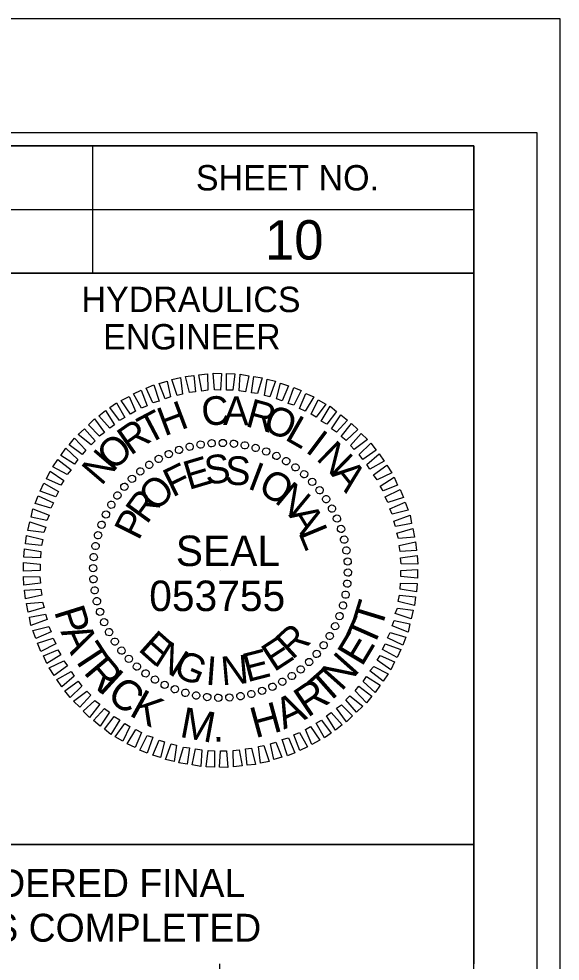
# Model space of a CAD drawing. Extents: x 1629737 to 1631945, y 1172886 to 1173986.
# Drawn here: x 1631314.8 to 1631421.3, y 1173800.4 to 1173985.9 of the extents above; entities that cross this region are included whole.
import ezdxf

# ---------------------------------------------------------------- set-up
doc = ezdxf.new("R2010")
doc.units = 0
for name, color, linetype in [('Sheet Data Field CELL', 7, 'Continuous'), ('Sheet PE Seal Cell', 7, 'Continuous'), ('Sheet Plot Border Inside CELL', 7, 'Continuous'), ('Sheet Plot Border Outside CELL', 7, 'Continuous'), ('Sheet Profile CELL', 7, 'Continuous'), ('Sheet Profile Grid Major CELL', 7, 'Continuous'), ('Sheet Sticker Exception Certification CELL', 7, 'Continuous')]:
    doc.layers.add(name, color=color, linetype=linetype)

msp = doc.modelspace()

# ---------------------------------------------------------------- linework, layer by layer
at = {"layer": 'Sheet PE Seal Cell'}
for p, q in [((1631350.58, 1173902.1), (1631350.58, 1173902.1)), ((1631352.73, 1173902.4), (1631352.73, 1173902.4)), ((1631354.93, 1173902.45), (1631354.93, 1173902.45)), ((1631357.13, 1173902.3), (1631357.13, 1173902.3)), ((1631344.28, 1173900.3), (1631344.28, 1173900.3)), ((1631346.28, 1173901.1), (1631346.28, 1173901.1)), ((1631348.38, 1173901.7), (1631348.38, 1173901.7)), ((1631359.28, 1173901.95), (1631359.28, 1173901.95)), ((1631361.38, 1173901.5), (1631361.38, 1173901.5)), ((1631363.48, 1173900.8), (1631363.48, 1173900.8)), ((1631342.33, 1173899.3), (1631342.33, 1173899.3)), ((1631365.48, 1173899.9), (1631365.48, 1173899.9)), ((1631367.43, 1173898.9), (1631367.43, 1173898.9)), ((1631338.68, 1173896.9), (1631338.68, 1173896.9)), ((1631340.43, 1173898.15), (1631340.43, 1173898.15)), ((1631369.23, 1173897.65), (1631369.23, 1173897.65)), ((1631337.03, 1173895.4), (1631337.03, 1173895.4)), ((1631370.98, 1173896.3), (1631370.98, 1173896.3)), ((1631372.53, 1173894.8), (1631372.53, 1173894.8)), ((1631335.53, 1173893.85), (1631335.53, 1173893.85)), ((1631374.03, 1173893.15), (1631374.03, 1173893.15)), ((1631334.18, 1173892.1), (1631334.18, 1173892.1)), ((1631375.28, 1173891.4), (1631375.28, 1173891.4)), ((1631332.93, 1173890.3), (1631332.93, 1173890.3)), ((1631376.43, 1173889.5), (1631376.43, 1173889.5)), ((1631331.93, 1173888.35), (1631331.93, 1173888.35)), ((1631377.43, 1173887.55), (1631377.43, 1173887.55)), ((1631331.03, 1173886.35), (1631331.03, 1173886.35)), ((1631378.23, 1173885.55), (1631378.23, 1173885.55)), ((1631330.33, 1173884.25), (1631330.33, 1173884.25)), ((1631329.88, 1173882.15), (1631329.88, 1173882.15)), ((1631378.83, 1173883.45), (1631378.83, 1173883.45)), ((1631329.53, 1173880), (1631329.53, 1173880)), ((1631379.23, 1173881.25), (1631379.23, 1173881.25)), ((1631379.53, 1173879.1), (1631379.53, 1173879.1)), ((1631329.38, 1173877.8), (1631329.38, 1173877.8)), ((1631354.48, 1173877.35), (1631354.48, 1173877.35)), ((1631379.58, 1173876.9), (1631379.58, 1173876.9)), ((1631329.43, 1173875.6), (1631329.43, 1173875.6)), ((1631379.43, 1173874.7), (1631379.43, 1173874.7)), ((1631329.73, 1173873.45), (1631329.73, 1173873.45)), ((1631379.08, 1173872.55), (1631379.08, 1173872.55)), ((1631330.13, 1173871.25), (1631330.13, 1173871.25)), ((1631330.73, 1173869.15), (1631330.73, 1173869.15)), ((1631378.63, 1173870.45), (1631378.63, 1173870.45)), ((1631331.53, 1173867.15), (1631331.53, 1173867.15)), ((1631377.93, 1173868.35), (1631377.93, 1173868.35)), ((1631332.53, 1173865.2), (1631332.53, 1173865.2)), ((1631377.03, 1173866.35), (1631377.03, 1173866.35)), ((1631333.68, 1173863.3), (1631333.68, 1173863.3)), ((1631376.03, 1173864.4), (1631376.03, 1173864.4)), ((1631334.93, 1173861.55), (1631334.93, 1173861.55)), ((1631374.78, 1173862.6), (1631374.78, 1173862.6)), ((1631336.43, 1173859.9), (1631336.43, 1173859.9)), ((1631373.43, 1173860.85), (1631373.43, 1173860.85)), ((1631337.98, 1173858.4), (1631337.98, 1173858.4)), ((1631370.28, 1173857.8), (1631370.28, 1173857.8)), ((1631371.93, 1173859.3), (1631371.93, 1173859.3)), ((1631339.73, 1173857.05), (1631339.73, 1173857.05)), ((1631341.53, 1173855.8), (1631341.53, 1173855.8)), ((1631368.53, 1173856.55), (1631368.53, 1173856.55)), ((1631343.48, 1173854.8), (1631343.48, 1173854.8)), ((1631345.48, 1173853.9), (1631345.48, 1173853.9)), ((1631364.68, 1173854.4), (1631364.68, 1173854.4)), ((1631366.63, 1173855.4), (1631366.63, 1173855.4)), ((1631347.58, 1173853.2), (1631347.58, 1173853.2)), ((1631349.68, 1173852.75), (1631349.68, 1173852.75)), ((1631351.83, 1173852.4), (1631351.83, 1173852.4)), ((1631354.03, 1173852.25), (1631354.03, 1173852.25)), ((1631356.23, 1173852.3), (1631356.23, 1173852.3)), ((1631358.38, 1173852.6), (1631358.38, 1173852.6)), ((1631360.58, 1173853), (1631360.58, 1173853)), ((1631362.68, 1173853.6), (1631362.68, 1173853.6))]:
    msp.add_line(p, q, dxfattribs=at)
for points in [[(1631345.98, 1173911.8), (1631344.93, 1173914.95), (1631346.63, 1173915.3), (1631347.03, 1173912.05)], [(1631348.38, 1173912.35), (1631347.58, 1173915.55), (1631349.23, 1173915.7), (1631349.58, 1173912.5)], [(1631350.78, 1173912.65), (1631350.23, 1173915.85), (1631351.93, 1173916.05), (1631351.98, 1173912.8)], [(1631353.28, 1173912.9), (1631353.03, 1173916.15), (1631354.68, 1173916.1), (1631354.48, 1173912.85)], [(1631355.68, 1173912.85), (1631355.68, 1173916.1), (1631357.33, 1173916.05), (1631356.88, 1173912.8)], [(1631358.18, 1173912.7), (1631358.38, 1173915.95), (1631360.03, 1173915.65), (1631359.38, 1173912.5)], [(1631360.58, 1173912.3), (1631361.03, 1173915.5), (1631362.68, 1173915.25), (1631361.78, 1173912.15)], [(1631341.13, 1173910.35), (1631339.83, 1173913.25), (1631341.33, 1173913.85), (1631342.38, 1173910.65)], [(1631343.58, 1173911.15), (1631342.43, 1173914.15), (1631343.98, 1173914.6), (1631344.63, 1173911.5)], [(1631363.13, 1173911.75), (1631363.63, 1173915), (1631365.33, 1173914.6), (1631364.18, 1173911.5)], [(1631365.53, 1173911.1), (1631366.28, 1173914.2), (1631367.83, 1173913.7), (1631366.58, 1173910.75)], [(1631367.78, 1173910.2), (1631368.93, 1173913.35), (1631370.33, 1173912.75), (1631368.93, 1173909.85)], [(1631336.78, 1173908.1), (1631334.93, 1173910.8), (1631336.48, 1173911.6), (1631337.73, 1173908.7)], [(1631338.93, 1173909.3), (1631337.33, 1173912.1), (1631338.88, 1173912.8), (1631340.03, 1173909.75)], [(1631370.03, 1173909.25), (1631371.28, 1173912.2), (1631372.83, 1173911.5), (1631371.13, 1173908.7)], [(1631334.58, 1173906.85), (1631332.73, 1173909.4), (1631334.03, 1173910.35), (1631335.68, 1173907.45)], [(1631372.33, 1173908.1), (1631373.68, 1173910.95), (1631375.18, 1173910.1), (1631373.28, 1173907.5)], [(1631374.28, 1173906.75), (1631376.03, 1173909.65), (1631377.33, 1173908.6), (1631375.38, 1173906.15)], [(1631332.68, 1173905.35), (1631330.53, 1173907.75), (1631331.88, 1173908.8), (1631333.63, 1173906)], [(1631376.33, 1173905.25), (1631378.18, 1173908), (1631379.48, 1173906.9), (1631377.28, 1173904.55)], [(1631330.68, 1173903.8), (1631328.48, 1173906), (1631329.68, 1173907.2), (1631331.63, 1173904.5)], [(1631378.23, 1173903.7), (1631380.28, 1173906.3), (1631381.48, 1173905.1), (1631379.18, 1173902.95)], [(1631329.03, 1173902.05), (1631326.48, 1173904.1), (1631327.73, 1173905.25), (1631329.83, 1173902.85)], [(1631380.03, 1173901.95), (1631382.18, 1173904.3), (1631383.38, 1173903.1), (1631380.78, 1173901.15)], [(1631327.28, 1173900.15), (1631324.68, 1173902.1), (1631325.78, 1173903.4), (1631327.98, 1173901.05)], [(1631381.78, 1173900.15), (1631384.08, 1173902.4), (1631385.13, 1173901.05), (1631382.48, 1173899.15)], [(1631325.78, 1173898.25), (1631323.08, 1173899.95), (1631324.03, 1173901.4), (1631326.43, 1173899.2)], [(1631383.28, 1173898.2), (1631385.73, 1173900.3), (1631386.68, 1173898.85), (1631383.88, 1173897.25)], [(1631324.28, 1173896.25), (1631321.48, 1173897.75), (1631322.48, 1173899.15), (1631325.08, 1173897.15)], [(1631323.08, 1173894.1), (1631320.23, 1173895.35), (1631320.98, 1173896.9), (1631323.68, 1173895.05)], [(1631384.58, 1173896.15), (1631387.23, 1173898.05), (1631388.18, 1173896.55), (1631385.28, 1173895.15)], [(1631385.88, 1173893.95), (1631388.68, 1173895.7), (1631389.33, 1173894.15), (1631386.48, 1173893)], [(1631322.08, 1173891.8), (1631318.98, 1173892.95), (1631319.73, 1173894.5), (1631322.58, 1173892.9)], [(1631386.88, 1173891.8), (1631389.83, 1173893.3), (1631390.48, 1173891.7), (1631387.38, 1173890.7)], [(1631321.08, 1173889.6), (1631317.98, 1173890.5), (1631318.63, 1173892.05), (1631321.63, 1173890.65)], [(1631320.33, 1173887.2), (1631317.23, 1173887.85), (1631317.58, 1173889.5), (1631320.73, 1173888.25)], [(1631387.78, 1173889.45), (1631390.83, 1173890.75), (1631391.38, 1173889.2), (1631388.28, 1173888.4)], [(1631388.58, 1173887.05), (1631391.78, 1173888.2), (1631392.08, 1173886.55), (1631388.93, 1173886)], [(1631319.68, 1173884.8), (1631316.58, 1173885.2), (1631316.93, 1173886.9), (1631320.08, 1173885.85)], [(1631389.18, 1173884.65), (1631392.33, 1173885.6), (1631392.63, 1173883.9), (1631389.48, 1173883.6)], [(1631319.28, 1173882.25), (1631316.08, 1173882.55), (1631316.28, 1173884.25), (1631319.53, 1173883.45)], [(1631389.63, 1173882.25), (1631392.88, 1173882.95), (1631393.03, 1173881.25), (1631389.83, 1173881.05)], [(1631319.03, 1173879.85), (1631315.78, 1173879.95), (1631315.88, 1173881.6), (1631319.13, 1173881.05)], [(1631389.93, 1173879.85), (1631393.18, 1173880.25), (1631393.28, 1173878.55), (1631390.03, 1173878.65)], [(1631318.98, 1173877.35), (1631315.73, 1173877.2), (1631315.73, 1173878.9), (1631318.98, 1173878.55)], [(1631319.03, 1173874.85), (1631315.78, 1173874.45), (1631315.68, 1173876.15), (1631318.93, 1173876.05)], [(1631389.98, 1173877.35), (1631393.23, 1173877.5), (1631393.23, 1173875.8), (1631389.98, 1173876.15)], [(1631389.93, 1173874.85), (1631393.18, 1173874.75), (1631393.08, 1173873.1), (1631389.83, 1173873.65)], [(1631319.33, 1173872.45), (1631316.08, 1173871.75), (1631315.93, 1173873.45), (1631319.13, 1173873.65)], [(1631389.68, 1173872.45), (1631392.88, 1173872.15), (1631392.68, 1173870.45), (1631389.43, 1173871.25)], [(1631319.78, 1173870.05), (1631316.63, 1173869.1), (1631316.33, 1173870.8), (1631319.48, 1173871.1)], [(1631320.38, 1173867.65), (1631317.18, 1173866.5), (1631316.88, 1173868.15), (1631320.03, 1173868.7)], [(1631389.28, 1173869.9), (1631392.38, 1173869.5), (1631392.03, 1173867.8), (1631388.88, 1173868.85)], [(1631388.63, 1173867.5), (1631391.73, 1173866.85), (1631391.38, 1173865.2), (1631388.23, 1173866.45)], [(1631321.18, 1173865.25), (1631318.13, 1173863.95), (1631317.58, 1173865.5), (1631320.68, 1173866.3)], [(1631387.88, 1173865.1), (1631390.98, 1173864.2), (1631390.33, 1173862.65), (1631387.33, 1173864.05)], [(1631322.08, 1173862.9), (1631319.13, 1173861.4), (1631318.48, 1173863), (1631321.58, 1173864)], [(1631323.08, 1173860.75), (1631320.28, 1173859), (1631319.63, 1173860.55), (1631322.48, 1173861.7)], [(1631386.88, 1173862.9), (1631389.98, 1173861.75), (1631389.23, 1173860.2), (1631386.38, 1173861.8)], [(1631324.38, 1173858.55), (1631321.73, 1173856.65), (1631320.78, 1173858.15), (1631323.68, 1173859.55)], [(1631385.88, 1173860.6), (1631388.73, 1173859.35), (1631387.98, 1173857.8), (1631385.28, 1173859.65)], [(1631384.68, 1173858.45), (1631387.48, 1173856.95), (1631386.48, 1173855.55), (1631383.88, 1173857.55)], [(1631325.68, 1173856.5), (1631323.23, 1173854.4), (1631322.28, 1173855.85), (1631325.08, 1173857.45)], [(1631383.18, 1173856.45), (1631385.88, 1173854.75), (1631384.93, 1173853.3), (1631382.53, 1173855.5)], [(1631327.18, 1173854.55), (1631324.88, 1173852.3), (1631323.83, 1173853.65), (1631326.48, 1173855.55)], [(1631381.68, 1173854.55), (1631384.28, 1173852.6), (1631383.18, 1173851.3), (1631380.98, 1173853.65)], [(1631328.93, 1173852.75), (1631326.78, 1173850.4), (1631325.58, 1173851.6), (1631328.18, 1173853.55)], [(1631379.93, 1173852.65), (1631382.48, 1173850.6), (1631381.23, 1173849.45), (1631379.13, 1173851.85)], [(1631330.73, 1173851), (1631328.68, 1173848.4), (1631327.48, 1173849.6), (1631329.78, 1173851.75)], [(1631332.63, 1173849.45), (1631330.78, 1173846.7), (1631329.48, 1173847.8), (1631331.68, 1173850.15)], [(1631378.28, 1173850.9), (1631380.48, 1173848.7), (1631379.28, 1173847.5), (1631377.33, 1173850.2)], [(1631334.68, 1173847.95), (1631332.93, 1173845.05), (1631331.63, 1173846.1), (1631333.58, 1173848.55)], [(1631376.28, 1173849.35), (1631378.43, 1173846.95), (1631377.08, 1173845.9), (1631375.33, 1173848.7)], [(1631336.63, 1173846.6), (1631335.28, 1173843.75), (1631333.78, 1173844.6), (1631335.68, 1173847.2)], [(1631372.18, 1173846.6), (1631374.03, 1173843.9), (1631372.48, 1173843.1), (1631371.23, 1173846)], [(1631374.38, 1173847.85), (1631376.23, 1173845.3), (1631374.93, 1173844.35), (1631373.28, 1173847.25)], [(1631338.93, 1173845.45), (1631337.68, 1173842.5), (1631336.13, 1173843.2), (1631337.83, 1173846)], [(1631341.18, 1173844.5), (1631340.03, 1173841.35), (1631338.63, 1173841.95), (1631340.03, 1173844.85)], [(1631370.03, 1173845.4), (1631371.63, 1173842.6), (1631370.08, 1173841.9), (1631368.93, 1173844.95)], [(1631343.43, 1173843.6), (1631342.68, 1173840.5), (1631341.13, 1173841), (1631342.38, 1173843.95)], [(1631345.83, 1173842.95), (1631345.33, 1173839.7), (1631343.63, 1173840.1), (1631344.78, 1173843.2)], [(1631362.98, 1173842.9), (1631364.03, 1173839.75), (1631362.33, 1173839.4), (1631361.93, 1173842.65)], [(1631365.38, 1173843.55), (1631366.53, 1173840.55), (1631364.98, 1173840.1), (1631364.33, 1173843.2)], [(1631367.83, 1173844.35), (1631369.13, 1173841.45), (1631367.63, 1173840.85), (1631366.58, 1173844.05)], [(1631348.38, 1173842.4), (1631347.93, 1173839.2), (1631346.28, 1173839.45), (1631347.18, 1173842.55)], [(1631350.78, 1173842), (1631350.58, 1173838.75), (1631348.93, 1173839.05), (1631349.58, 1173842.2)], [(1631353.28, 1173841.85), (1631353.28, 1173838.6), (1631351.63, 1173838.65), (1631352.08, 1173841.9)], [(1631355.68, 1173841.8), (1631355.93, 1173838.55), (1631354.28, 1173838.6), (1631354.48, 1173841.85)], [(1631358.18, 1173842.05), (1631358.73, 1173838.85), (1631357.03, 1173838.65), (1631356.98, 1173841.9)], [(1631360.58, 1173842.35), (1631361.38, 1173839.15), (1631359.73, 1173839), (1631359.38, 1173842.2)]]:
    msp.add_lwpolyline(points, close=True, dxfattribs=at)
for centre, major_axis in [((1631348.42, 1173901.69), (-0.174, 0.699)), ((1631350.56, 1173902.12), (-0.113, 0.711)), ((1631352.73, 1173902.37), (-0.05, 0.718)), ((1631354.92, 1173902.43), (0.013, 0.72)), ((1631357.11, 1173902.29), (0.075, 0.716)), ((1631359.27, 1173901.97), (0.137, 0.707)), ((1631361.4, 1173901.46), (0.198, 0.692)), ((1631344.28, 1173900.26), (-0.293, 0.658)), ((1631346.32, 1173901.07), (-0.234, 0.681)), ((1631363.47, 1173900.77), (0.258, 0.672)), ((1631365.48, 1173899.89), (0.316, 0.647)), ((1631340.46, 1173898.14), (-0.403, 0.597)), ((1631342.33, 1173899.29), (-0.349, 0.63)), ((1631367.4, 1173898.85), (0.371, 0.617)), ((1631369.23, 1173897.64), (0.423, 0.582)), ((1631338.7, 1173896.84), (-0.453, 0.56)), ((1631370.94, 1173896.28), (0.472, 0.543)), ((1631335.56, 1173893.81), (-0.543, 0.472)), ((1631337.06, 1173895.39), (-0.5, 0.518)), ((1631372.53, 1173894.77), (0.518, 0.5)), ((1631334.19, 1173892.09), (-0.582, 0.423)), ((1631373.98, 1173893.14), (0.56, 0.453)), ((1631332.99, 1173890.27), (-0.617, 0.371)), ((1631375.28, 1173891.38), (0.597, 0.403)), ((1631331.94, 1173888.35), (-0.647, 0.316)), ((1631376.42, 1173889.51), (0.63, 0.349)), ((1631377.4, 1173887.55), (0.658, 0.293)), ((1631331.07, 1173886.34), (-0.672, 0.258)), ((1631378.2, 1173885.52), (0.681, 0.234)), ((1631330.38, 1173884.26), (-0.692, 0.198)), ((1631378.82, 1173883.42), (0.699, 0.174)), ((1631329.87, 1173882.14), (-0.707, 0.137)), ((1631379.26, 1173881.28), (0.711, 0.113)), ((1631329.54, 1173879.97), (-0.716, 0.075)), ((1631379.5, 1173879.1), (0.718, 0.05)), ((1631329.41, 1173877.79), (-0.72, 0.013)), ((1631329.47, 1173875.6), (-0.718, -0.05)), ((1631379.56, 1173876.91), (0.72, -0.013)), ((1631329.71, 1173873.43), (-0.711, -0.113)), ((1631379.43, 1173874.73), (0.716, -0.075)), ((1631379.1, 1173872.57), (0.707, -0.137)), ((1631330.15, 1173871.28), (-0.699, -0.174)), ((1631378.59, 1173870.44), (0.692, -0.198)), ((1631330.77, 1173869.19), (-0.681, -0.234)), ((1631377.9, 1173868.36), (0.672, -0.258)), ((1631331.57, 1173867.15), (-0.658, -0.293)), ((1631377.03, 1173866.36), (0.647, -0.316)), ((1631332.55, 1173865.19), (-0.63, -0.349)), ((1631375.98, 1173864.43), (0.617, -0.371)), ((1631333.69, 1173863.33), (-0.597, -0.403)), ((1631374.77, 1173862.61), (0.582, -0.423)), ((1631334.99, 1173861.57), (-0.56, -0.453)), ((1631373.41, 1173860.9), (0.543, -0.472)), ((1631336.44, 1173859.93), (-0.518, -0.5)), ((1631371.91, 1173859.31), (0.5, -0.518)), ((1631338.03, 1173858.42), (-0.472, -0.543)), ((1631339.74, 1173857.06), (-0.423, -0.582)), ((1631370.27, 1173857.86), (0.453, -0.56)), ((1631341.57, 1173855.85), (-0.371, -0.617)), ((1631366.64, 1173855.42), (0.349, -0.63)), ((1631368.51, 1173856.56), (0.403, -0.597)), ((1631343.49, 1173854.81), (-0.316, -0.647)), ((1631345.5, 1173853.94), (-0.258, -0.672)), ((1631347.57, 1173853.24), (-0.198, -0.692)), ((1631360.55, 1173853.02), (0.174, -0.699)), ((1631362.65, 1173853.64), (0.234, -0.681)), ((1631364.69, 1173854.44), (0.293, -0.658)), ((1631349.7, 1173852.73), (-0.137, -0.707)), ((1631351.86, 1173852.41), (-0.075, -0.716)), ((1631354.05, 1173852.28), (-0.013, -0.72)), ((1631356.23, 1173852.33), (0.05, -0.718)), ((1631358.41, 1173852.58), (0.113, -0.711))]:
    msp.add_ellipse(centre, major_axis=major_axis, ratio=0.999708, dxfattribs=at)
at = {"layer": 'Sheet Plot Border Inside CELL'}
msp.add_lwpolyline([(1629750.31, 1172908.39), (1631416.81, 1172908.39), (1631416.81, 1173963.49), (1629750.31, 1173963.49)], close=True, dxfattribs=at)
at = {"layer": 'Sheet Plot Border Outside CELL'}
msp.add_lwpolyline([(1629737.31, 1172885.94), (1631421.31, 1172885.94), (1631421.31, 1173985.94), (1629737.31, 1173985.94)], close=True, dxfattribs=at)
at = {"layer": 'Sheet Profile CELL'}
for p, q in [((1631329.31, 1173960.89), (1631329.31, 1173935.89)), ((1631204.26, 1173948.39), (1631404.31, 1173948.39))]:
    msp.add_line(p, q, dxfattribs=at)
for points in [[(1631404.31, 1173960.94), (1629904.31, 1173960.94), (1629904.31, 1172910.94), (1631404.31, 1172910.94)], [(1631204.26, 1173960.94), (1631404.31, 1173960.94), (1631404.31, 1173935.89), (1631204.26, 1173935.89)], [(1631304.31, 1173935.89), (1631404.31, 1173935.89), (1631404.31, 1173823.39), (1631304.31, 1173823.39)]]:
    msp.add_lwpolyline(points, close=True, dxfattribs=at)
at = {"layer": 'Sheet Profile Grid Major CELL'}
msp.add_lwpolyline([(1631354.31, 1173799.89), (1631354.31, 1173460.94), (1631404.31, 1173460.94), (1631404.31, 1173810.94)], dxfattribs=at)
at = {"layer": 'Sheet Sticker Exception Certification CELL'}
for p, q in [((1631204.26, 1173823.39), (1631404.3, 1173823.39)), ((1631404.3, 1173823.38), (1631404.3, 1173799.88))]:
    msp.add_line(p, q, dxfattribs=at)

# ---------------------------------------------------------------- texts
at = {"layer": 'Sheet Data Field CELL'}
msp.add_text('10', height=7.75, dxfattribs=at).set_placement((1631363.23, 1173938.55))
at = {"layer": 'Sheet PE Seal Cell'}
for s, height, rotation, p in [('C', 5.64, 6.2199, (1631351.03, 1173905.7)), ('A', 5.64, 359.0203, (1631354.98, 1173906)), ('H', 5.64, 20.6195, (1631343.43, 1173903.7)), ('R', 5.64, 344.6211, (1631359.18, 1173905.8)), ('O', 5.64, 337.4212, (1631362.53, 1173905.05)), ('T', 5.64, 27.8198, (1631340.18, 1173902.05)), ('L', 5.64, 330.2209, (1631366.93, 1173903.2)), ('R', 5.64, 35.0205, (1631336.78, 1173899.85)), ('I', 5.64, 323.0201, (1631370.98, 1173900.8)), ('O', 5.64, 42.2217, (1631333.33, 1173896.75)), ('N', 5.64, 315.8189, (1631373.13, 1173899.25)), ('N', 5.64, 49.4235, (1631331.03, 1173893.85)), ('S', 5.64, 7.2556, (1631351.68, 1173894.2)), ('F', 5.64, 25.967, (1631345.03, 1173891.65)), ('E', 5.64, 16.6111, (1631348.23, 1173893.15)), ('S', 5.64, 357.9004, (1631355.28, 1173894.25)), ('I', 5.64, 339.1896, (1631359.58, 1173893.55)), ('O', 5.64, 329.8335, (1631361.58, 1173892.85)), ('A', 5.64, 308.6172, (1631376.08, 1173896.3)), ('O', 5.64, 44.6812, (1631341.73, 1173888.7)), ('N', 5.64, 320.4766, (1631364.93, 1173890.85)), ('R', 5.64, 54.0397, (1631339.98, 1173886.25)), ('P', 5.64, 63.3989, (1631338.38, 1173883.05)), ('A', 5.64, 301.7603, (1631367.78, 1173888.25)), ('L', 5.64, 292.4009, (1631369.73, 1173884.8)), ('SEAL', 5.998, 360, (1631345.69, 1173878.2)), ('T', 6, 72.9557, (1631386.09, 1173865.47)), ('P', 6, 287.3534, (1631321.69, 1173869.3)), ('T', 6, 66.1555, (1631384.46, 1173861.82)), ('A', 6, 294.4627, (1631322.94, 1173865.3)), ('E', 5.64, 318.2769, (1631338.08, 1173861.7)), ('R', 5.64, 42.4814, (1631368.58, 1173859.6)), ('E', 6, 59.0461, (1631382.31, 1173858.22)), ('T', 6, 303.303, (1631325.17, 1173860.6)), ('N', 5.64, 327.634, (1631341.08, 1173859)), ('E', 5.64, 33.1241, (1631365.03, 1173857.25)), ('G', 5.64, 336.9902, (1631344.88, 1173856.75)), ('E', 5.64, 14.4118, (1631359.73, 1173855.3)), ('N', 6, 48.3203, (1631378.26, 1173853.38)), ('R', 6, 310.1033, (1631327.36, 1173857.24)), ('I', 5.64, 355.7012, (1631351.43, 1173854.85)), ('N', 5.64, 5.0564, (1631354.78, 1173854.7)), ('I', 6, 317.5835, (1631330.21, 1173853.88)), ('T', 6, 41.5201, (1631375.26, 1173850.73)), ('C', 6, 321.3855, (1631331.82, 1173852.32)), ('K', 6, 330.9676, (1631336.3, 1173848.9)), ('R', 6, 34.0398, (1631371.62, 1173848.26)), ('A', 6, 25.1995, (1631366.94, 1173845.97)), ('M', 6, 349.4519, (1631346.26, 1173844.6)), ('H', 6, 15.2155, (1631361.31, 1173844.28)), ('.', 6, 0.9814, (1631352.97, 1173843.62))]:
    msp.add_text(s, height=height, rotation=rotation, dxfattribs=at).set_placement(p)
msp.add_text('053755', height=5.998, dxfattribs=at).set_placement((1631340.45, 1173869.34))
at = {"layer": 'Sheet Profile CELL'}
for s, p in [('SHEET NO.', (1631349.63, 1173952.15)), ('HYDRAULICS', (1631327.13, 1173928.2)), ('ENGINEER', (1631331.38, 1173920.85))]:
    msp.add_text(s, height=5, rotation=360, dxfattribs=at).set_placement(p)
at = {"layer": 'Sheet Sticker Exception Certification CELL'}
for s, p in [('DOCUMENT NOT CONSIDERED FINAL', (1631225.33, 1173813.04)), ('UNLESS ALL SIGNATURES COMPLETED', (1631220.26, 1173804.24))]:
    msp.add_text(s, height=5.5, rotation=360, dxfattribs=at).set_placement(p)

doc.saveas('drawing.dxf')
